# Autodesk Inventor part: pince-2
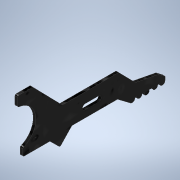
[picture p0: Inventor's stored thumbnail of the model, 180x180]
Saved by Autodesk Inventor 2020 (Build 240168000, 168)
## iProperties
Created: 2021-10
Part Number: pince-2
Material: Générique
Document SubType Name: Modeling
Designer: bruno
Density: 1 g/cm^3
Appearance: Noir
Author: bruno
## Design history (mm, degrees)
sketch "Esquisse1"
  geometry: L1 (-4.155, -25.629)-(-4.155, -30.629); L2 (-6.155, -25.629)-(-6.155, -30.629); L3 (7.691, -0.438)-(10.446, -0.438); L4 (-7.207, -2.346)-(-9.233, -2.346); L5 (8.1, -6.586)-(8.1, -6.58); L6 (-11.258, -0.35)-(-11.258, -0.438); L7 (-0.354, -38.146)-(-0.354, -17.123); L8 (-9.733, -12.473)-(-13.092, -15.878); L9 (-6.724, -44.413)-(-8.393, -53.057); L10 (-8.393, -53.057)-(-10.196, -55.455); L11 (-10.196, -55.455)-(-11.607, -55.455); L12 (-12.297, -55.455)-(-12.297, -55.165); L13 (-11.588, -44.203)-(-11.588, -44.904); L14 (-13.08, -16.591)-(-8.776, -20.676); L15 (-8.776, -20.676)-(-8.776, -37.72); L16 (-11.607, -52.755)-(-11.607, -53.455); L17 (-11.596, -46.903)-(-11.596, -47.627); L18 (-11.596, -49.577)-(-11.596, -50.755); L19 (-11.588, -43.757)-(-11.596, -43.741); L20 (-4.7, -24.661)-(-4.7, -29.925); L21 (-0.354, -38.146)-(-0.354, -38.16); L22 (-9.733, -12.473)-(-9.733, -5.167); L23 (10.946, -6.1)-(-0.354, -17.123); L24 (10.946, -4.623)-(10.946, -6.1); L25 (-9.733, -5.167)-(-9.733, -2.846); L26 (-11.607, -54.455)-(-11.207, -54.455); L27 (-0.354, -38.16)-(-6.724, -44.413); L28 (-8.776, -37.72)-(-12.453, -42.615); L29 (-11.588, -14.346)-(-11.596, -14.356); L30 (-13.055, -16.614)-(-13.055, -16.615); L31 (10.946, -4.623)-(10.946, -0.938); C1 r 1.75 at (-5.176, -35.629); C2 r 1.75 at (-5.176, -20.629); A1 r 1 centre (-5.155, -30.629) between (-6.155, -30.629) and (-4.155, -30.629); A2 r 1 centre (-5.155, -25.629) between (-4.155, -25.629) and (-6.155, -25.629); A3 r 7.248 centre (0, 0) between (-6.742, -2.662) and (7.195, -0.878); A4 r 0.5 centre (7.691, -0.938) between (7.691, -0.438) and (7.195, -0.878); A5 r 0.5 centre (-7.207, -2.846) between (-6.742, -2.662) and (-7.207, -2.346); A6 r 1 centre (-11.646, -43.205) between (-12.453, -42.615) and (-11.588, -44.203); A7 r 1 centre (-11.562, -45.904) between (-11.588, -44.904) and (-11.596, -46.903); A8 r 1 centre (-11.818, -48.602) between (-11.596, -47.627) and (-11.596, -49.577); A9 r 1 centre (-11.607, -51.755) between (-11.596, -50.755) and (-11.607, -52.755); A10 r 1 centre (-11.607, -54.455) between (-11.607, -53.455) and (-11.607, -55.455); A11 r 0.5 centre (-12.736, -16.229) between (-13.092, -15.878) and (-13.08, -16.591); A12 r 10.964 centre (0, 0) between (-10.953, -0.495) and (-10.951, -0.523); A13 r 0.5 centre (-10.233, -4.159) between (-9.926, -3.764) and (-9.93, -3.761); A14 r 0.5 centre (-9.233, -2.846) between (-9.233, -2.346) and (-9.733, -2.846); A15 r 10.961 centre (0, 0) between (-10.953, -0.418) and (-10.952, -0.438); A16 r 0.5 centre (10.446, -0.938) between (10.946, -0.938) and (10.446, -0.438); 26 further points
  constraints: 64 end point, 34 point on circle, 18 centre point, 13 point on line, 12 tangent, 9 vertical, 5 coincident, 4 perpendicular, 3 horizontal, 2 parallel, 1 midpoint
  dimensions: "d44" = 2 diameter of A1; "d45" = 2 diameter of A2; "d46" = 5 distance of A1.centre A2.centre; "d67" = 12 distance from line of L4 L29.start; "d81" = 3 distance of L9.end L10.end; "d83" = 2 diameter of A7; "d84" = 2 diameter of A6; "d85" = 2 diameter of A8; "d86" = 2 diameter of A9; "d87" = 2.7 distance of A6.centre A7.centre; "d107" = 0.4 distance of L26.start L26.end; "d108" = 3.5 diameter of C1; "d109" = 3.5 diameter of C2; "d110" = 3.6 distance from line of C1.centre L15; "d111" = 3.6 distance from line of L15 C2.centre; "d112" = 15 distance of C2.centre C1.centre; "d113" = 5 vertical distance of A2.centre C2.centre; "d114" = 0.5 radius of A16
extrude "Extrusion4" new body sketch "Esquisse1" distance "d70" = 1; taper "d71" = 0 deg
node "Solide2"
other parameters: "d5" = 22.5, "d76" = 5, "d78" = 3.5, "d99" = 0.5 (derived), "d100" = 0.5 (derived)
